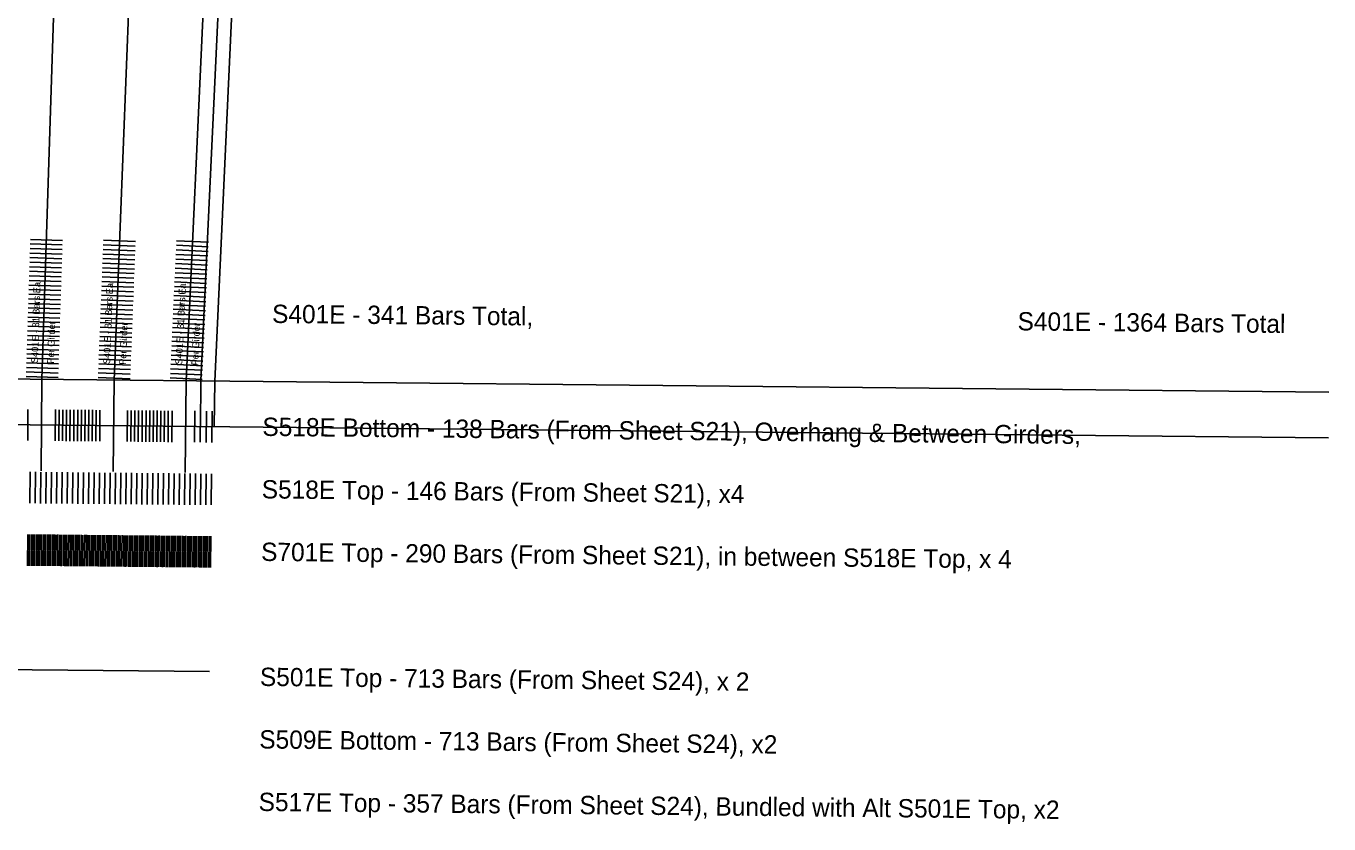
# Model space of a CAD drawing. Extents: x 632276 to 635000, y 381313 to 381846.
# Drawn here: x 634855.3 to 634997.7, y 381351.8 to 381439 of the extents above; entities that cross this region are included whole.
import ezdxf

# ---------------------------------------------------------------- set-up
doc = ezdxf.new("R2010")
doc.units = 0
for name, color, linetype in [('B_Boring Annot', 7, 'Continuous'), ('B_No_Plot', 7, 'Continuous'), ('R_Border_Scale', 7, 'Continuous'), ('R_Shade Removal', 7, 'Continuous'), ('R_Wall', 7, 'Continuous')]:
    doc.layers.add(name, color=color, linetype=linetype)

msp = doc.modelspace()

# ---------------------------------------------------------------- linework, layer by layer
at = {"layer": 'B_Boring Annot'}
for p, q in [((634874.43, 381400.26), (634884.62, 381620.17)), ((634875.93, 381400.19), (634886.11, 381620.1)), ((634874.38, 381395.2), (634874.43, 381400.2)), ((634875.88, 381395.19), (634875.93, 381400.19))]:
    msp.add_line(p, q, dxfattribs=at)
at = {"layer": 'B_No_Plot'}
for p, q in [((634669.11, 381402.24), (634997.75, 381398.98)), ((634669.06, 381397.25), (634997.7, 381393.98))]:
    msp.add_line(p, q, dxfattribs=at)
at = {"layer": 'R_Border_Scale'}
for p, q in [((634859.27, 381415.06), (634855.77, 381415.17)), ((634859.29, 381415.56), (634855.79, 381415.67)), ((634867.27, 381415.43), (634863.77, 381415.57)), ((634875.26, 381415.36), (634871.76, 381415.52)), ((634859.22, 381413.56), (634855.73, 381413.68)), ((634859.24, 381414.06), (634855.74, 381414.17)), ((634859.26, 381414.56), (634855.76, 381414.67)), ((634867.21, 381413.93), (634863.71, 381414.07)), ((634867.23, 381414.43), (634863.73, 381414.57)), ((634867.25, 381414.93), (634863.75, 381415.07)), ((634875.19, 381413.86), (634871.69, 381414.02)), ((634875.21, 381414.36), (634871.71, 381414.52)), ((634875.23, 381414.86), (634871.74, 381415.02)), ((634859.19, 381412.56), (634855.69, 381412.68)), ((634859.21, 381413.06), (634855.71, 381413.18)), ((634867.15, 381412.43), (634863.66, 381412.57)), ((634867.17, 381412.93), (634863.68, 381413.07)), ((634867.19, 381413.43), (634863.7, 381413.57)), ((634875.12, 381412.36), (634871.62, 381412.52)), ((634875.14, 381412.86), (634871.64, 381413.02)), ((634875.16, 381413.36), (634871.67, 381413.52)), ((634859.14, 381411.07), (634855.65, 381411.18)), ((634859.16, 381411.56), (634855.66, 381411.68)), ((634859.18, 381412.06), (634855.68, 381412.18)), ((634867.09, 381410.93), (634863.6, 381411.07)), ((634867.11, 381411.43), (634863.62, 381411.57)), ((634867.13, 381411.93), (634863.64, 381412.07)), ((634875.05, 381410.86), (634871.55, 381411.02)), ((634875.07, 381411.36), (634871.57, 381411.52)), ((634875.09, 381411.86), (634871.6, 381412.02)), ((634859.1, 381409.57), (634855.6, 381409.68)), ((634859.11, 381410.07), (634855.61, 381410.18)), ((634859.13, 381410.57), (634855.63, 381410.68)), ((634867.04, 381409.43), (634863.54, 381409.57)), ((634867.06, 381409.93), (634863.56, 381410.07)), ((634867.08, 381410.43), (634863.58, 381410.57)), ((634874.98, 381409.36), (634871.48, 381409.53)), ((634875, 381409.86), (634871.51, 381410.02)), ((634875.02, 381410.36), (634871.53, 381410.52)), ((634859.05, 381408.07), (634855.55, 381408.18)), ((634859.07, 381408.57), (634855.57, 381408.68)), ((634859.08, 381409.07), (634855.58, 381409.18)), ((634866.98, 381407.93), (634863.48, 381408.07)), ((634867, 381408.43), (634863.5, 381408.57)), ((634867.02, 381408.93), (634863.52, 381409.07)), ((634874.91, 381407.86), (634871.41, 381408.03)), ((634874.93, 381408.36), (634871.44, 381408.53)), ((634874.96, 381408.86), (634871.46, 381409.03)), ((634859, 381406.57), (634855.5, 381406.68)), ((634859.02, 381407.07), (634855.52, 381407.18)), ((634859.03, 381407.57), (634855.54, 381407.68)), ((634866.92, 381406.44), (634863.42, 381406.57)), ((634866.94, 381406.94), (634863.44, 381407.07)), ((634866.96, 381407.43), (634863.46, 381407.57)), ((634874.86, 381406.87), (634871.37, 381407.03)), ((634874.89, 381407.37), (634871.39, 381407.53)), ((634858.95, 381405.07), (634855.46, 381405.18)), ((634858.97, 381405.57), (634855.47, 381405.68)), ((634858.99, 381406.07), (634855.49, 381406.18)), ((634866.88, 381405.44), (634863.38, 381405.57)), ((634866.9, 381405.94), (634863.4, 381406.07)), ((634874.79, 381405.37), (634871.3, 381405.53)), ((634874.82, 381405.87), (634871.32, 381406.03)), ((634874.84, 381406.37), (634871.34, 381406.53)), ((634858.92, 381404.07), (634855.42, 381404.18)), ((634858.94, 381404.57), (634855.44, 381404.68)), ((634866.82, 381403.94), (634863.32, 381404.07)), ((634866.84, 381404.44), (634863.34, 381404.57)), ((634866.86, 381404.94), (634863.36, 381405.07)), ((634874.72, 381403.87), (634871.23, 381404.03)), ((634874.75, 381404.37), (634871.25, 381404.53)), ((634874.77, 381404.87), (634871.27, 381405.03)), ((634858.87, 381402.57), (634855.38, 381402.68)), ((634858.89, 381403.07), (634855.39, 381403.18)), ((634858.91, 381403.57), (634855.41, 381403.68)), ((634866.76, 381402.44), (634863.27, 381402.58)), ((634866.78, 381402.94), (634863.28, 381403.07)), ((634866.8, 381403.44), (634863.3, 381403.57)), ((634874.65, 381402.37), (634871.16, 381402.53)), ((634874.68, 381402.87), (634871.18, 381403.03)), ((634874.7, 381403.37), (634871.2, 381403.53)), ((634858.83, 381401.07), (634855.33, 381401.18)), ((634858.84, 381401.57), (634855.34, 381401.68)), ((634858.86, 381402.07), (634855.36, 381402.18)), ((634866.7, 381400.94), (634863.21, 381401.08)), ((634866.72, 381401.44), (634863.23, 381401.58)), ((634866.74, 381401.94), (634863.25, 381402.08)), ((634874.58, 381400.87), (634871.09, 381401.03)), ((634874.61, 381401.37), (634871.11, 381401.53)), ((634874.63, 381401.87), (634871.13, 381402.03)), ((634858.81, 381400.57), (634855.31, 381400.68)), ((634866.68, 381400.44), (634863.19, 381400.58)), ((634874.56, 381400.37), (634871.07, 381400.53)), ((634855.49, 381393.68), (634855.52, 381397.1)), ((634858.49, 381393.65), (634858.52, 381397.07)), ((634858.89, 381393.65), (634858.93, 381397.06)), ((634859.3, 381393.65), (634859.33, 381397.06)), ((634859.7, 381393.64), (634859.74, 381397.06)), ((634860.11, 381393.64), (634860.14, 381397.05)), ((634860.52, 381393.63), (634860.55, 381397.05)), ((634860.92, 381393.63), (634860.96, 381397.04)), ((634861.33, 381393.63), (634861.36, 381397.04)), ((634861.74, 381393.62), (634861.77, 381397.04)), ((634862.14, 381393.62), (634862.18, 381397.03)), ((634862.55, 381393.61), (634862.58, 381397.03)), ((634862.95, 381393.61), (634862.99, 381397.02)), ((634863.36, 381393.61), (634863.39, 381397.02)), ((634866.36, 381393.58), (634866.39, 381396.99)), ((634866.77, 381393.57), (634866.8, 381396.99)), ((634867.17, 381393.57), (634867.21, 381396.98)), ((634867.58, 381393.56), (634867.61, 381396.98)), ((634867.99, 381393.56), (634868.02, 381396.97)), ((634868.39, 381393.56), (634868.43, 381396.97)), ((634868.8, 381393.55), (634868.83, 381396.97)), ((634869.2, 381393.55), (634869.24, 381396.96)), ((634869.61, 381393.54), (634869.64, 381396.96)), ((634870.02, 381393.54), (634870.05, 381396.95)), ((634870.42, 381393.54), (634870.46, 381396.95)), ((634870.83, 381393.53), (634870.86, 381396.95)), ((634871.24, 381393.53), (634871.27, 381396.94)), ((634873.74, 381393.5), (634873.77, 381396.92)), ((634874.36, 381393.5), (634874.39, 381396.91)), ((634874.99, 381393.49), (634875.02, 381396.9)), ((634875.61, 381393.48), (634875.64, 381396.9)), ((634855.73, 381386.85), (634855.76, 381390.26)), ((634856.31, 381386.84), (634856.34, 381390.26)), ((634856.89, 381386.83), (634856.93, 381390.25)), ((634857.48, 381386.83), (634857.51, 381390.24)), ((634858.06, 381386.82), (634858.09, 381390.24)), ((634858.64, 381386.82), (634858.68, 381390.23)), ((634859.22, 381386.81), (634859.26, 381390.23)), ((634859.81, 381386.8), (634859.84, 381390.22)), ((634860.39, 381386.8), (634860.42, 381390.21)), ((634860.97, 381386.79), (634861.01, 381390.21)), ((634861.55, 381386.79), (634861.59, 381390.2)), ((634862.14, 381386.78), (634862.17, 381390.2)), ((634862.72, 381386.78), (634862.75, 381390.19)), ((634863.3, 381386.77), (634863.34, 381390.18)), ((634863.89, 381386.76), (634863.92, 381390.18)), ((634864.47, 381386.76), (634864.5, 381390.17)), ((634865.05, 381386.75), (634865.09, 381390.17)), ((634865.63, 381386.75), (634865.67, 381390.16)), ((634866.22, 381386.74), (634866.25, 381390.15)), ((634866.8, 381386.73), (634866.83, 381390.15)), ((634867.38, 381386.73), (634867.42, 381390.14)), ((634867.96, 381386.72), (634868, 381390.14)), ((634868.55, 381386.72), (634868.58, 381390.13)), ((634869.13, 381386.71), (634869.16, 381390.12)), ((634869.71, 381386.7), (634869.75, 381390.12)), ((634870.3, 381386.7), (634870.33, 381390.11)), ((634870.88, 381386.69), (634870.91, 381390.11)), ((634871.46, 381386.69), (634871.5, 381390.1)), ((634872.04, 381386.68), (634872.08, 381390.1)), ((634872.63, 381386.67), (634872.66, 381390.09)), ((634873.21, 381386.67), (634873.24, 381390.08)), ((634873.79, 381386.66), (634873.83, 381390.08)), ((634874.37, 381386.66), (634874.41, 381390.07)), ((634874.96, 381386.65), (634874.99, 381390.07)), ((634875.54, 381386.65), (634875.58, 381390.07)), ((634855.47, 381380.02), (634855.5, 381383.44)), ((634855.66, 381380.02), (634855.69, 381383.43)), ((634855.86, 381380.02), (634855.89, 381383.43)), ((634856.05, 381380.02), (634856.08, 381383.43)), ((634856.24, 381380.01), (634856.28, 381383.43)), ((634856.44, 381380.01), (634856.47, 381383.43)), ((634856.63, 381380.01), (634856.67, 381383.43)), ((634856.82, 381380.01), (634856.86, 381383.42)), ((634857.02, 381380.01), (634857.05, 381383.42)), ((634857.21, 381380.01), (634857.25, 381383.42)), ((634857.41, 381380), (634857.44, 381383.41)), ((634857.6, 381380), (634857.64, 381383.42)), ((634857.8, 381380), (634857.83, 381383.42)), ((634857.99, 381379.99), (634858.02, 381383.41)), ((634858.19, 381380), (634858.22, 381383.41)), ((634858.38, 381380), (634858.41, 381383.41)), ((634858.57, 381379.99), (634858.61, 381383.4)), ((634858.77, 381379.99), (634858.8, 381383.41)), ((634858.96, 381379.99), (634859, 381383.4)), ((634859.16, 381379.98), (634859.19, 381383.4)), ((634859.35, 381379.99), (634859.39, 381383.4)), ((634859.55, 381379.98), (634859.58, 381383.4)), ((634859.74, 381379.98), (634859.77, 381383.39)), ((634859.93, 381379.98), (634859.97, 381383.39)), ((634860.13, 381379.98), (634860.16, 381383.39)), ((634860.32, 381379.97), (634860.36, 381383.38)), ((634860.52, 381379.97), (634860.55, 381383.39)), ((634860.71, 381379.97), (634860.75, 381383.39)), ((634860.9, 381379.96), (634860.94, 381383.38)), ((634861.1, 381379.97), (634861.13, 381383.38)), ((634861.29, 381379.97), (634861.33, 381383.38)), ((634861.49, 381379.96), (634861.52, 381383.37)), ((634861.68, 381379.96), (634861.72, 381383.38)), ((634861.88, 381379.96), (634861.91, 381383.38)), ((634862.07, 381379.95), (634862.1, 381383.37)), ((634862.27, 381379.96), (634862.3, 381383.37)), ((634862.46, 381379.95), (634862.49, 381383.37)), ((634862.65, 381379.95), (634862.69, 381383.36)), ((634862.85, 381379.95), (634862.88, 381383.37)), ((634863.04, 381379.95), (634863.08, 381383.36)), ((634863.23, 381379.94), (634863.27, 381383.35)), ((634863.43, 381379.94), (634863.46, 381383.36)), ((634863.62, 381379.94), (634863.66, 381383.36)), ((634863.82, 381379.93), (634863.85, 381383.35)), ((634864.01, 381379.94), (634864.05, 381383.35)), ((634864.21, 381379.94), (634864.24, 381383.35)), ((634864.4, 381379.93), (634864.43, 381383.34)), ((634864.6, 381379.93), (634864.63, 381383.35)), ((634864.79, 381379.93), (634864.82, 381383.35)), ((634864.98, 381379.92), (634865.02, 381383.34)), ((634865.18, 381379.93), (634865.21, 381383.34)), ((634865.37, 381379.93), (634865.41, 381383.34)), ((634865.57, 381379.92), (634865.6, 381383.33)), ((634865.76, 381379.92), (634865.8, 381383.34)), ((634865.96, 381379.92), (634865.99, 381383.33)), ((634866.15, 381379.91), (634866.18, 381383.33)), ((634866.34, 381379.92), (634866.38, 381383.33)), ((634866.54, 381379.91), (634866.57, 381383.33)), ((634866.73, 381379.9), (634866.77, 381383.32)), ((634866.93, 381379.91), (634866.96, 381383.32)), ((634867.12, 381379.91), (634867.16, 381383.32)), ((634867.31, 381379.9), (634867.35, 381383.31)), ((634867.51, 381379.9), (634867.54, 381383.32)), ((634867.7, 381379.9), (634867.74, 381383.32)), ((634867.9, 381379.89), (634867.93, 381383.31)), ((634868.09, 381379.9), (634868.13, 381383.31)), ((634868.29, 381379.9), (634868.32, 381383.31)), ((634868.48, 381379.89), (634868.51, 381383.3)), ((634868.68, 381379.89), (634868.71, 381383.31)), ((634868.87, 381379.89), (634868.9, 381383.31)), ((634869.06, 381379.88), (634869.1, 381383.3)), ((634869.26, 381379.89), (634869.29, 381383.3)), ((634869.45, 381379.89), (634869.49, 381383.3)), ((634869.64, 381379.87), (634869.68, 381383.29)), ((634869.84, 381379.88), (634869.87, 381383.3)), ((634870.03, 381379.88), (634870.07, 381383.29)), ((634870.23, 381379.87), (634870.26, 381383.28)), ((634870.42, 381379.88), (634870.46, 381383.29)), ((634870.62, 381379.87), (634870.65, 381383.29)), ((634870.81, 381379.86), (634870.84, 381383.28)), ((634871.01, 381379.87), (634871.04, 381383.28)), ((634871.2, 381379.87), (634871.23, 381383.28)), ((634871.39, 381379.86), (634871.43, 381383.27)), ((634871.59, 381379.86), (634871.62, 381383.28)), ((634871.78, 381379.86), (634871.82, 381383.28)), ((634871.98, 381379.85), (634872.01, 381383.27)), ((634872.17, 381379.86), (634872.21, 381383.27)), ((634872.37, 381379.86), (634872.4, 381383.27)), ((634872.56, 381379.85), (634872.59, 381383.26)), ((634872.75, 381379.85), (634872.79, 381383.27)), ((634872.95, 381379.85), (634872.98, 381383.26)), ((634873.14, 381379.84), (634873.18, 381383.25)), ((634873.34, 381379.85), (634873.37, 381383.26)), ((634873.53, 381379.84), (634873.57, 381383.26)), ((634873.72, 381379.83), (634873.76, 381383.25)), ((634873.92, 381379.84), (634873.95, 381383.26)), ((634874.11, 381379.84), (634874.15, 381383.25)), ((634874.31, 381379.83), (634874.34, 381383.24)), ((634874.5, 381379.83), (634874.54, 381383.25)), ((634874.7, 381379.83), (634874.73, 381383.25)), ((634874.89, 381379.82), (634874.92, 381383.24)), ((634875.09, 381379.83), (634875.12, 381383.24)), ((634875.28, 381379.83), (634875.31, 381383.24)), ((634875.47, 381379.83), (634875.51, 381383.24)), ((634875.36, 381368.44), (634815.36, 381369.03))]:
    msp.add_line(p, q, dxfattribs=at)
at = {"layer": 'R_Shade Removal'}
for p, q in [((634864.04, 381620.32), (634857.05, 381400.38)), ((634864.93, 381400.3), (634873.52, 381620.22)), ((634882.99, 381620.13), (634872.8, 381400.22)), ((634857.05, 381400.38), (634856.95, 381390.38)), ((634864.93, 381400.3), (634864.83, 381390.3)), ((634872.8, 381400.22), (634872.7, 381390.21))]:
    msp.add_line(p, q, dxfattribs=at)

# ---------------------------------------------------------------- texts
at = {"layer": 'R_Wall'}
for s, height, rotation, p in [('S401E - 31 Bars Ea,', 0.75, 88.19, (634856.61, 381402.14)), ('S401E - 31 Bars Ea,', 0.75, 87.7697, (634864.49, 381402.03)), ('S401E - 31 Bars Ea,', 0.75, 87.3558, (634872.38, 381401.98)), ('S401E - 341 Bars Total,', 2, 359.4304, (634882.2, 381406.54)), ('Per Girder', 0.75, 88.19, (634858.36, 381402.09)), ('Per Girder', 0.75, 87.7697, (634866.24, 381401.96)), ('S401E - 1364 Bars Total', 2, 359.4304, (634963.7, 381405.73)), ('Per Girder', 0.75, 87.3558, (634874.13, 381401.89)), ('S518E Bottom - 138 Bars (From Sheet S21), Overhang & Between Girders,', 2, 359.4304, (634881.14, 381394.2)), ('S518E Top - 146 Bars (From Sheet S21), x4', 2, 359.4304, (634881.07, 381387.37)), ('S701E Top - 290 Bars (From Sheet S21), in between S518E Top, x 4', 2, 359.4304, (634881, 381380.54)), ('S501E Top - 713 Bars (From Sheet S24), x 2', 2, 359.4304, (634880.87, 381366.88)), ('S509E Bottom - 713 Bars (From Sheet S24), x2', 2, 359.4304, (634880.8, 381360.05)), ('S517E Top - 357 Bars (From Sheet S24), Bundled with Alt S501E Top, x2', 2, 359.4304, (634880.73, 381353.22))]:
    msp.add_text(s, height=height, rotation=rotation, dxfattribs=at).set_placement(p)

doc.saveas('drawing.dxf')
